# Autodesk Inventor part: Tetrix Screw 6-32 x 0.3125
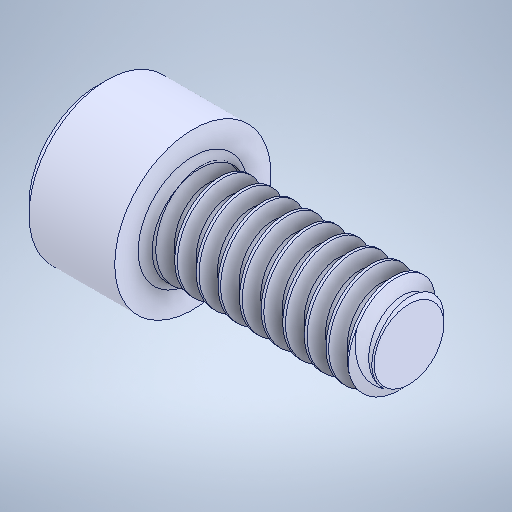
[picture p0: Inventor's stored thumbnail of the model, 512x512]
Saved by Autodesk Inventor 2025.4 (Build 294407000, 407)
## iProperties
Created: 2021-10
Part Number: Tetrix Screw 6-32 x 0.3125
Material: Genérico
Document SubType Name: Modeling
Designer: usuario
Density: 1 g/cm^3
Appearance: Valor por defecto
Author: usuario
Sending System: SolidWorks 2016
Last Author: LENOVO
Last Saved: 2021-10-22
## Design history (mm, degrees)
chamfer "Chamfer1"
node "Sólido1"
